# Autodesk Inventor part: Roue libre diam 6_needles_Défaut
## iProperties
Shininess: 64.0
Length Units: 11269
Angle Units: 11279
Time Units: 11290
Mass Units: 11283
Length Display Precision: 3
Angle Display Precision: 2
Compacted: True
Part Number: Roue libre diam 6_needles_Défaut
Document SubType Name: Modeling
Created: 2006-01
Material: Par défaut
Designer: riri
Density: 0.0
Volumn: 0.0
Area: 0.0
PropertySet Name: Model Information
Control State: 0
Master: False
Checked Out: False
Author: riri
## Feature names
1. Base1
